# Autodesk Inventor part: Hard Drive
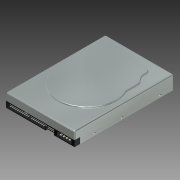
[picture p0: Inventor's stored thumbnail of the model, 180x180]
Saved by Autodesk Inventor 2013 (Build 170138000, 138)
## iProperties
Company: Autodesk Inc.
Created: 2005-12
Part Number: Hard Drive
Document SubType Name: Modeling
Designer: Autodesk Inc.
Density: 1 g/cm^3
Mass: 263.467 g
Surface Area: 454.657 cm^2
Volume: 263.467 cm^3
Material: Allgemein
Title: Personal Computer
Author: Autodesk Inc.
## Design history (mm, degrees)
sketch "Sketch1"
  geometry: L1 (0, 70)-(0, -70) reference; L2 (-22, 0)-(132, 0) reference; L3 (0, 50)-(110, 50); L4 (110, 50)-(110, -50); L5 (110, -50)-(0, -50); L6 (0, -50)-(0, 50)
  constraints: 8 end point, 2 parallel, 1 horizontal, 1 perpendicular, 1 point on line, 1 other
  dimensions: "d0" = 100 distance of L3.end L4.end; "d1" = 110 distance of L3.start L3.end
extrude "Extrusion1" new body sketch "Sketch1" distance "d2" = 1; taper "d3" = 0 deg
sketch "Sketch2"
  geometry: L1 (0, -50)-(0, 50) reference; L2 (0, 45.779)-(103, 45.779); L3 (103, 45.779)-(103, -45.779); L4 (103, -45.779)-(0, -45.779); L5 (0, -45.779)-(0, 45.779); L6 (-22, 0)-(132, 0) reference; 1 other entity
  constraints: 1 collinear, 3 other
  dimensions: "d5" = 103 distance of L3.end L4.end
feature "Decal1" sketch "Sketch2"
sketch "Sketch3"
  geometry: L1 (110, 50)-(110, -50) reference; L2 (0, 50)-(110, 50) reference; L3 (0, -50)-(0, 50) reference; L4 (110, -50)-(0, -50) reference; L5 (0, 45.298)-(80.942, 45.298); L6 (80.942, 45.298)-(80.942, 31.993); L7 (80.942, 31.993)-(86.165, 31.993); L8 (86.165, 31.993)-(86.165, 14.211); L9 (86.165, 14.211)-(77.087, 14.211); L10 (77.087, 14.211)-(62.912, 24.159); L11 (62.912, 24.159)-(60.3, 21.796); L12 (60.3, 21.796)-(37.296, 21.796); L13 (37.296, 21.796)-(34.312, -5.436); L14 (34.312, -5.436)-(37.296, -5.436); L15 (37.296, -5.436)-(47.368, -24.585); L16 (47.368, -24.585)-(61.917, -24.585); L17 (61.917, -24.585)-(64.453, -27.389); L18 (64.453, -27.389)-(76.093, -27.389); L19 (76.093, -27.389)-(80.227, -31.959); L20 (80.227, -31.959)-(93.874, -31.959); L21 (93.874, -31.959)-(98.226, -33.787); L22 (98.226, -33.787)-(102.206, -33.787); L23 (102.206, -33.787)-(102.206, -45.103); L24 (102.206, -45.103)-(0, -45.103)
  constraints: 40 end point, 12 parallel, 3 perpendicular, 2 point on line
extrude "Extrusion2" cut sketch "Sketch3" stored distance "d6" = 1; taper "d7" = 0 deg
sketch "Sketch5"
  geometry: L1 (80.942, 45.298)-(0, 45.298) reference; L2 (0, -45.103)-(0, 45.298) reference; L3 (0, -45.103)-(102.206, -45.103) reference; L4 (86.165, 14.211)-(86.165, 31.993) reference; C1 r 2.75 at (10.6, -42.103); C2 r 2.75 at (65, -42.353); C3 r 2.75 at (10, 42.548); C4 r 2.75 at (82.665, 27.298)
  constraints: 4 centre point, 3 equal radius, 2 tangent
  dimensions: "d11" = 10.6 distance from line of L2 C1.centre; "d12" = 5.5 diameter of C1; "d13" = 65 distance from line of L2 C2.centre; "d14" = 3 distance from line of L3 C1.centre; "d15" = 10 distance from line of L2 C3.centre; "d16" = 3.5 distance from line of L4 C4.centre; "d17" = 18 distance from line of L1 C4.centre
extrude "Extrusion3" join sketch "Sketch5" distance "d18" = 1.5; taper "d19" = 0 deg
sketch "Sketch6"
  geometry: L1 (0, 1.768)-(1.768, 0); L2 (1.768, 0)-(0, -1.768); L3 (0, -1.768)-(-1.768, 0); L4 (-1.768, 0)-(0, 1.768); L5 (1.25, 1.25)-(1.25, -1.25); L6 (1.25, -1.25)-(-1.25, -1.25); L7 (-1.25, -1.25)-(-1.25, 1.25); L8 (-1.25, 1.25)-(1.25, 1.25); L9 (54.4, 1.518)-(56.168, -0.25); L10 (56.168, -0.25)-(54.4, -2.018); L11 (54.4, -2.018)-(52.632, -0.25); L12 (52.632, -0.25)-(54.4, 1.518); L13 (55.651, 0.999)-(55.649, -1.501); L14 (55.649, -1.501)-(53.149, -1.499); L15 (53.149, -1.499)-(53.151, 1.001); L16 (53.151, 1.001)-(55.651, 0.999); L17 (-0.6, 86.418)-(1.168, 84.651); L18 (1.168, 84.651)-(-0.6, 82.883); L19 (-0.6, 82.883)-(-2.368, 84.651); L20 (-2.368, 84.651)-(-0.6, 86.418); L21 (0.648, 85.902)-(0.652, 83.402); L22 (0.652, 83.402)-(-1.848, 83.399); L23 (-1.848, 83.399)-(-1.852, 85.899); L24 (-1.852, 85.899)-(0.648, 85.902); L25 (73.314, 70.651)-(73.315, 68.151); L26 (73.315, 68.151)-(70.815, 68.15); L27 (70.815, 68.15)-(70.814, 70.65); L28 (70.814, 70.65)-(73.314, 70.651); L29 (72.067, 71.168)-(73.833, 69.399); L30 (73.833, 69.399)-(72.063, 67.633); L31 (72.063, 67.633)-(70.297, 69.403); L32 (70.297, 69.403)-(72.067, 71.168); C1 r 2.75 at (0, 0) reference; C2 r 2.75 at (54.4, -0.25) reference; C3 r 2.75 at (-0.6, 84.651) reference; C4 r 2.75 at (72.065, 69.401) reference; 8 further points
  constraints: 64 end point, 8 coincident, 7 equal length, 56 other
  dimensions: "d20" = 2.5 distance of L5.end L6.end
extrude "Extrusion4" cut sketch "Sketch6" distance "d21" = 0.5; taper "d22" = 0 deg
sketch "Sketch7"
  geometry: L1 (0, -45.103)-(0, 45.298) reference; L2 (-165, 0)-(38, 0) reference; L3 (9, 50)-(-136, 50); L4 (-136, 50)-(-136, -50); L5 (-136, -50)-(9, -50); L6 (9, -50)-(9, 50)
  constraints: 8 end point, 2 parallel, 1 horizontal, 1 perpendicular, 1 other
  dimensions: "d23" = 9 distance between parallel lines of L1 L6; "d24" = 145 distance of L3.start L3.end; "d25" = 100 distance of L5.end L3.start
extrude "Extrusion5" join sketch "Sketch7" distance "d26" = 16; taper "d27" = 0 deg
sketch "Sketch8"
  geometry: L1 (-9, 50)-(136, 50) reference; L2 (136, -50)-(-9, -50) reference; L3 (136, 50)-(136, -50) reference; L4 (0, 70)-(0, -70) reference; L5 (0, 50)-(-9, 50); L6 (-9, 50)-(-9, -50); L7 (-9, -50)-(0, -50); L8 (0, -50)-(0, 50); L9 (0, -45.103)-(136, -45.103); L10 (136, -45.103)-(136, -50); L11 (136, -50)-(0, -50); L12 (0, -50)-(0, -45.103); L13 (0, 50)-(136, 50); L14 (136, 50)-(136, 45.298); L15 (136, 45.298)-(0, 45.298); L16 (0, 45.298)-(0, 50); L17 (80.942, 45.298)-(10, 45.298) reference; C1 r 3 at (30.639, 46.538); C2 r 3 at (31.662, -45.103); C3 r 3 at (76.04, -45.103); 1 further point
  constraints: 24 end point, 6 parallel, 5 point on line, 3 centre point, 3 horizontal, 3 perpendicular, 2 equal radius, 1 collinear
  dimensions: "d30" = 6 diameter of C1
extrude "Extrusion6" join sketch "Sketch8" distance "d28" = 4; taper "d29" = 0 deg
sketch "Sketch9" dims "d18" = 1.5, "d19" = 0
  geometry: L1 (-38, 0)-(165, 0) reference; L2 (-9, -50)-(-9, 50) reference; L3 (59, 0)-(45.76, 17.57); L4 (59, 0)-(50.404, -20.251); L5 (59, 0)-(80.836, 2.681); A1 r 19 centre (59, 0) between (41.264, 6.815) and (57.338, 18.927); A2 r 2.5 centre (45.76, 17.57) between (43.26, 17.57) and (46.449, 19.973); A3 r 2.5 centre (50.404, -20.251) between (47.978, -20.856) and (51.654, -22.416); A4 r 2.5 centre (80.836, 2.681) between (82.573, 0.883) and (82.086, 4.846); A5 r 30 centre (13.26, 17.574) between (41.264, 6.815) and (43.26, 17.57); A6 r 30 centre (54.714, 48.812) between (46.449, 19.973) and (57.338, 18.927); A7 r 30 centre (18.87, -28.118) between (47.978, -20.856) and (43.44, -10.903); A8 r 30 centre (66.65, -48.399) between (61.966, -18.767) and (51.654, -22.416); A9 r 30 centre (103.416, -20.694) between (82.573, 0.883) and (76.222, -8.024); A10 r 30 centre (97.09, 30.825) between (73.77, 11.952) and (82.086, 4.846)
  constraints: 24 point on circle, 12 tangent, 10 centre point, 7 equal radius, 6 end point, 3 coincident, 2 equal length, 1 point on line
  dimensions: "d31" = 68 distance from line of L2 L3.start; "d32" = 38 diameter of A1; "d33" = 120 deg angle of L4 L3; "d34" = 120 deg angle of L5 L3; "d35" = 53 deg angle of L1 L3; "d36" = 22 distance of L3.start L3.end; "d38" = 5 diameter of A4; "d39" = 30 radius of A5
extrude "Extrusion7" join sketch "Sketch9" distance "d40" = 0.5; taper "d41" = 0 deg
sketch "Sketch10"
  geometry: C1 r 17.5 at (59, 0); C2 r 1.5 at (45.76, 17.57); C3 r 1.5 at (50.404, -20.251); C4 r 1.5 at (80.836, 2.681); A1 r 2.5 centre (50.404, -20.251) between (47.978, -20.856) and (51.654, -22.416) reference; A2 r 2.5 centre (80.836, 2.681) between (82.573, 0.883) and (82.086, 4.846) reference; A3 r 2.5 centre (45.76, 17.57) between (46.449, 19.973) and (43.26, 17.57) reference; A4 r 19 centre (59, 0) between (41.264, 6.815) and (43.44, -10.903) reference
  constraints: 4 centre point, 4 coincident, 2 equal radius
  dimensions: "d42" = 35 diameter of C1; "d43" = 3 diameter of C2
extrude "Extrusion8" join sketch "Sketch10" distance "d44" = 2; taper "d45" = 0 deg
extrude "Extrusion9" join sketch "Sketch10" distance "d46" = 1; taper "d47" = 0 deg
sketch "Sketch11"
  geometry: L1 (37.296, 21.796)-(34.312, -5.436) reference; L2 (36.418, 13.783)-(34.784, -1.128); L3 (34.784, -1.128)-(49.805, -2.774); L4 (49.805, -2.774)-(51.439, 12.137); L5 (51.439, 12.137)-(36.418, 13.783)
  constraints: 8 end point, 2 parallel, 2 point on line, 1 perpendicular
  dimensions: "d48" = 15 distance of L3.end L4.end
extrude "Extrusion10" join sketch "Sketch11" distance "d49" = 1.2; taper "d50" = 0 deg
sketch "Sketch12"
  geometry: L1 (36.418, 13.783)-(46.892, 12.635) reference; L2 (41.601, -1.875)-(34.784, -1.128) reference; L3 (36.146, 11.298)-(35.982, 9.807); L4 (35.982, 9.807)-(47.523, 8.542); L5 (47.523, 8.542)-(47.686, 10.033); L6 (47.686, 10.033)-(36.146, 11.298); L7 (35.841, 8.514)-(35.677, 7.023); L8 (35.677, 7.023)-(47.004, 5.782); L9 (47.004, 5.782)-(47.168, 7.273); L10 (47.168, 7.273)-(35.841, 8.514); L11 (35.536, 5.731)-(35.372, 4.24); L12 (35.372, 4.24)-(46.183, 3.055); L13 (46.183, 3.055)-(46.346, 4.546); L14 (46.346, 4.546)-(35.536, 5.731); L15 (35.22, 2.848)-(35.056, 1.357); L16 (35.056, 1.357)-(44.115, 0.365); L17 (44.115, 0.365)-(44.278, 1.856); L18 (44.278, 1.856)-(35.22, 2.848)
  constraints: 32 end point, 8 parallel, 4 perpendicular, 9 other
  dimensions: "d51" = 1.5 distance between parallel lines of L4 L6; "d52" = 1.5 distance between parallel lines of L8 L10 (= d51); "d53" = 1.5 distance between parallel lines of L12 L14 (= d51); "d54" = 1.5 distance between parallel lines of L16 L18 (= d53); "d55" = 2.5 distance between parallel lines of L6 L1; "d56" = 2.5 distance between parallel lines of L2 L16 (= d55); "d57" = 1.3 distance between parallel lines of L10 L4; "d58" = 1.3 distance between parallel lines of L14 L8 (= d57); "d59" = 1.4 distance between parallel lines of L18 L12 (derived)
extrude "Extrusion11" cut sketch "Sketch12" distance "d60" = 0.3; taper "d61" = 0 deg
sketch "Sketch13"
  geometry: L1 (102.206, -45.103)-(136, -45.103) reference; L2 (136, 45.298)-(136, -45.103) reference; L3 (136, 45.298)-(128, 45.298); L4 (128, 45.298)-(128, -45.103); L5 (128, -45.103)-(136, -45.103); L6 (136, -45.103)-(136, 45.298)
  constraints: 8 end point, 2 parallel, 1 horizontal, 1 perpendicular, 1 point on line
  dimensions: "d62" = 8 distance between parallel lines of L2 L4
extrude "Extrusion12" join sketch "Sketch13" stored distance "d63" = 0.2; taper "d64" = 0 deg
workplane "Work Plane1"
sketch "Sketch14"
  geometry: L1 (-38, 0)-(165, 0) reference; L2 (90.225, 25)-(90.225, 46.356); L3 (90.225, -25)-(90.225, -28.671); L4 (90.225, -28.671)-(105.059, -28.671); L5 (105.059, -28.671)-(105.059, -46.421); L6 (59, 0)-(114.438, 46.518); L7 (59, 0)-(130.851, 26.152); L8 (59, 0)-(132.237, -26.656); L9 (105.059, -33.978)-(129.579, -33.978); L10 (90.225, 26.201)-(114.438, 46.518); L11 (96.588, 13.681)-(130.851, 26.152); L12 (99, 0)-(132.69, 0); L13 (96.588, -13.681)-(130.464, -26.011); L14 (105.059, -33.978)-(131.043, -33.978); C1 r 17.5 at (59, 0) reference; A1 r 40 centre (59, 0) between (90.225, -25) and (90.225, 25)
  constraints: 26 end point, 9 point on line, 5 point on circle, 3 collinear, 3 perpendicular, 1 centre point, 1 coincident, 1 parallel, 1 symmetric about line
  dimensions: "d66" = 40 radius of A1; "d67" = 50 distance of L3.start L2.start; "d68" = 20 deg angle of L1 L7; "d69" = 20 deg angle of L6 L7; "d70" = 20 deg angle of L8 L1
feature "Rib1" sketch "Sketch14" dims "d71" = 4, "d72" = 1
sketch "Sketch15"
  geometry: L1 (-136, -50)-(-136, 50) reference; L2 (9, -50)-(-136, -50) reference; L3 (-78.033, 38)-(-98.033, 38); L4 (-98.033, 38)-(-108.033, 30); L5 (-108.033, 30)-(-121, 30); L6 (-121, 30)-(-121, -20); L7 (-121, -20)-(-108.109, -20); L8 (-108.109, -20)-(-83.109, -35); L9 (-165, 0)-(38, 0) reference; A1 r 17.5 centre (-59, 0) between (-46.892, 12.635) and (-41.601, -1.875) reference; A2 r 42.5 centre (-59, 0) between (-78.033, 38) and (-83.109, -35); A3 r 42.5 centre (-59, 0) between (-83.109, -35) and (-78.033, 38)
  constraints: 12 end point, 4 point on circle, 3 parallel, 2 centre point, 2 coincident, 1 perpendicular
  dimensions: "d73" = 85 diameter of A2; "d74" = 50 distance of L5.end L6.end; "d75" = 30 distance between parallel lines of L9 L5; "d76" = 15 distance between parallel lines of L1 L6; "d77" = 20 distance of L3.start L3.end; "d78" = 38 distance between parallel lines of L9 L3; "d79" = 10 horizontal distance of L3.end L4.end; "d80" = 25 horizontal distance of L7.end L8.end; "d81" = 15 vertical distance of L7.end L8.end
extrude "Extrusion13" join sketch "Sketch15" distance "d82" = 2; taper "d83" = 0 deg
fillet "Fillet1" dims "d84" = 5, "d85" = 10
fillet "Fillet2" dims "d86" = 1
sketch "Sketch16"
  geometry: L1 (20, 0)-(0, 0) reference; L2 (20, 0)-(20, 100) reference; L3 (0, 100)-(20, 100) reference; L4 (19, 95.7)-(12.5, 95.7); L5 (12.5, 95.7)-(12.5, 74.36); L6 (12.5, 74.36)-(19, 74.36); L7 (19, 74.36)-(19, 95.7); L8 (12.6, 70.08)-(19, 70.08); L9 (19, 70.08)-(19, 1); L10 (19, 1)-(12.6, 1); L11 (12.6, 1)-(12.6, 70.08)
  constraints: 16 end point, 4 parallel, 2 horizontal, 2 perpendicular, 1 collinear
  dimensions: "d87" = 4.3 distance between parallel lines of L4 L3; "d88" = 21.34 distance of L6.end L4.start; "d89" = 1 distance between parallel lines of L2 L7; "d90" = 6.5 distance of L4.start L4.end; "d91" = 1 distance between parallel lines of L1 L10; "d159" = 6.4 distance between parallel lines of L11 L9; "d163" = 69.08 distance of L8.end L9.end
extrude "Extrusion14" cut sketch "Sketch16" distance "d93" = 6.2; taper "d94" = 0 deg
chamfer "Chamfer1" distance "d95" = 1.63; stored, may be unused: second distance "d96" = 2, angle "d97" = 45 deg
sketch "Sketch17" dims "d79" = 10
  geometry: L1 (19, 70.08)-(19, 1) reference; L2 (20, 0)-(20, 100) reference; L3 (19, 57.88)-(16, 57.88); L4 (16, 57.88)-(16, 56.88); L5 (16, 56.88)-(19, 56.88); L6 (19, 56.88)-(19, 57.88); L7 (19, 1)-(12.6, 1) reference
  constraints: 8 end point, 2 parallel, 1 horizontal, 1 perpendicular, 1 point on line
  dimensions: "d98" = 4 distance between parallel lines of L2 L4; "d99" = 1 distance between parallel lines of L5 L3; "d161" = 55.88 distance between parallel lines of L7 L5
extrude "Extrusion15" join sketch "Sketch17" stored distance "d101" = 8; taper "d102" = 0 deg
sketch "Sketch18"
  geometry: L1 (12.6, 70.08)-(19, 70.08) reference; L2 (20, 0)-(20, 100) reference; L3 (19, 57.88)-(20, 57.88); L4 (20, 57.88)-(20, 70.08); L5 (20, 70.08)-(19, 70.08); L6 (19, 70.08)-(19, 57.88)
  constraints: 8 end point, 2 parallel, 1 collinear, 1 horizontal, 1 perpendicular, 1 point on line
extrude "Extrusion16" cut sketch "Sketch18" distance "d103" = 3; taper "d104" = 0 deg
sketch "Sketch19"
  geometry: L1 (19, 57.88)-(19, 70.08) reference; L2 (19, 70.08)-(12.6, 70.08) reference; L3 (12.6, 70.08)-(12.6, 1) reference; C1 r 0.5 at (17.07, 67.54)
  constraints: 1 centre point
  dimensions: "d105" = 6.4 distance between parallel lines of L1 L3 (derived); "d106" = 1.93 distance from line of C1.centre L1 (computed from d105); "d107" = 1 diameter of C1; "d108" = 12.2 distance of L1.start L1.end (derived); "d109" = 2.54 distance from line of C1.centre L2
extrude "Extrusion17" join sketch "Sketch19" distance "d110" = 5; taper "d111" = 0 deg
pattern_linear "Rectangular Pattern1" dims "d114" = 2.54, "d117" = 2.54
sketch "Sketch20"
  geometry: L1 (16, 56.88)-(16, 57.88) reference; L2 (17.07, 59.92)-(17.07, 50.611); L3 (12.6, 70.08)-(12.6, 1) reference; L4 (19, 1)-(19, 56.88) reference; L5 (19, 28.94)-(12.6, 28.94); L6 (15.8, 28.94)-(15.8, 32.971); C1 r 0.5 at (17.07, 59.92) reference; C2 r 0.5 at (17.07, 53.07)
  constraints: 6 end point, 2 midpoint, 2 perpendicular, 2 point on line, 1 centre point, 1 parallel
  dimensions: "d118" = 1 diameter of C2; "d120" = 55.88 distance of L4.start L4.end (derived); "d162" = 48.26 diameter of C2.centre L5
extrude "Extrusion18" join sketch "Sketch20" distance "d121" = 5; taper "d122" = 0 deg
sketch "Sketch21"
  geometry: L1 (0, 100)-(20, 100) reference; L2 (20, 0)-(0, 0) reference; L3 (12.5, 75.99)-(12.5, 94.07) reference; L4 (11.7, 100)-(11.3, 100); L5 (11.3, 100)-(11.3, 0); L6 (11.3, 0)-(11.7, 0); L7 (11.7, 0)-(11.7, 100)
  constraints: 8 end point, 2 parallel, 2 point on line, 1 horizontal, 1 perpendicular
  dimensions: "d129" = 0.8 distance between parallel lines of L3 L7; "d130" = 0.4 distance between parallel lines of L7 L5
extrude "Extrusion19" cut sketch "Sketch21" distance "d131" = 8; taper "d132" = 0 deg
sketch "Sketch22"
  geometry: L1 (11.3, 0)-(11.3, 100) reference; L2 (12.6, 1)-(12.6, 70.08) reference; L3 (12.6, 26.908)-(11.3, 26.908); L4 (11.3, 26.908)-(11.3, 30.972); L5 (11.3, 30.972)-(12.6, 30.972); L6 (12.6, 30.972)-(12.6, 26.908); L7 (19, 1)-(19, 56.88) reference; 2 further points
  constraints: 8 end point, 2 midpoint, 2 parallel, 2 point on line, 1 horizontal, 1 horizontal alignment, 1 perpendicular
  dimensions: "d164" = 4.064 distance between parallel lines of L3 L5
extrude "Extrusion20" cut sketch "Sketch22" stored distance "d133" = 8; taper "d134" = 0 deg
sketch "Sketch23"
  geometry: L1 (14.13, 74.36)-(19, 74.36) reference; L2 (19, 74.36)-(19, 95.7) reference; L3 (19, 95.7)-(14.13, 95.7) reference; L4 (15.75, 95.7)-(15.75, 74.36); C1 r 1 at (15.75, 91.432); C2 r 1 at (15.75, 87.164); C3 r 1 at (15.75, 82.896); C4 r 1 at (15.75, 78.628)
  constraints: 6 point on line, 4 centre point, 3 equal radius, 2 end point, 1 perpendicular
  dimensions: "d135" = 3.25 distance between parallel lines of L2 L4; "d136" = 21.34 distance of L4.start L4.end (derived); "d137" = 4.268 distance from line of C1.centre L3 (= 0.2 x d136); "d138" = 4.268 distance of C2.centre C1.centre (= d137); "d139" = 4.268 distance of C3.centre C2.centre (= d138); "d140" = 4.268 distance of C4.centre C3.centre (= d139); "d141" = 2 diameter of C1
extrude "Extrusion21" join sketch "Sketch23" distance "d142" = 6.1; taper "d143" = 0 deg
fillet "Fillet3" dims "d144" = 1
split "Split2"
sketch "Sketch26"
  geometry: L1 (0, 11.3)-(0, 0) reference; L2 (145, 20)-(145, 0) reference; L3 (145, 20)-(8, 20) reference; C1 r 1.5 at (29, 17); C2 r 1.5 at (69, 17); C3 r 1.5 at (125, 17)
  constraints: 3 centre point, 2 equal radius, 2 horizontal alignment
  dimensions: "d145" = 29 distance from line of C1.centre L1; "d146" = 69 distance from line of C2.centre L1; "d147" = 20 distance from line of L2 C3.centre; "d148" = 3 distance from line of L3 C1.centre; "d149" = 3 diameter of C1
extrude "Extrusion22" cut sketch "Sketch26" distance "d150" = 6; taper "d151" = 0 deg
mirror "Mirror1"
fillet "Fillet4" dims "d158" = 2
body "Solid1"
pattern_linear "Rectangular Pattern2" dims "d125" = 2.54, "d128" = 2.54
node "Image1"
node "Projected Loop1"
node "Projected Loop2"
sketch "Sketch25"
  geometry: L1 (8, -11.7)-(0, -11.7); L2 (0, -11.7)-(0, -20); L3 (0, -20)-(8, -20); L4 (8, -20)-(8, -11.7)
  constraints: 8 end point, 2 parallel, 1 horizontal, 1 perpendicular
other parameters: "d65" = -2.5
